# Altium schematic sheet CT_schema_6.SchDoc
size 277 x 170 mm
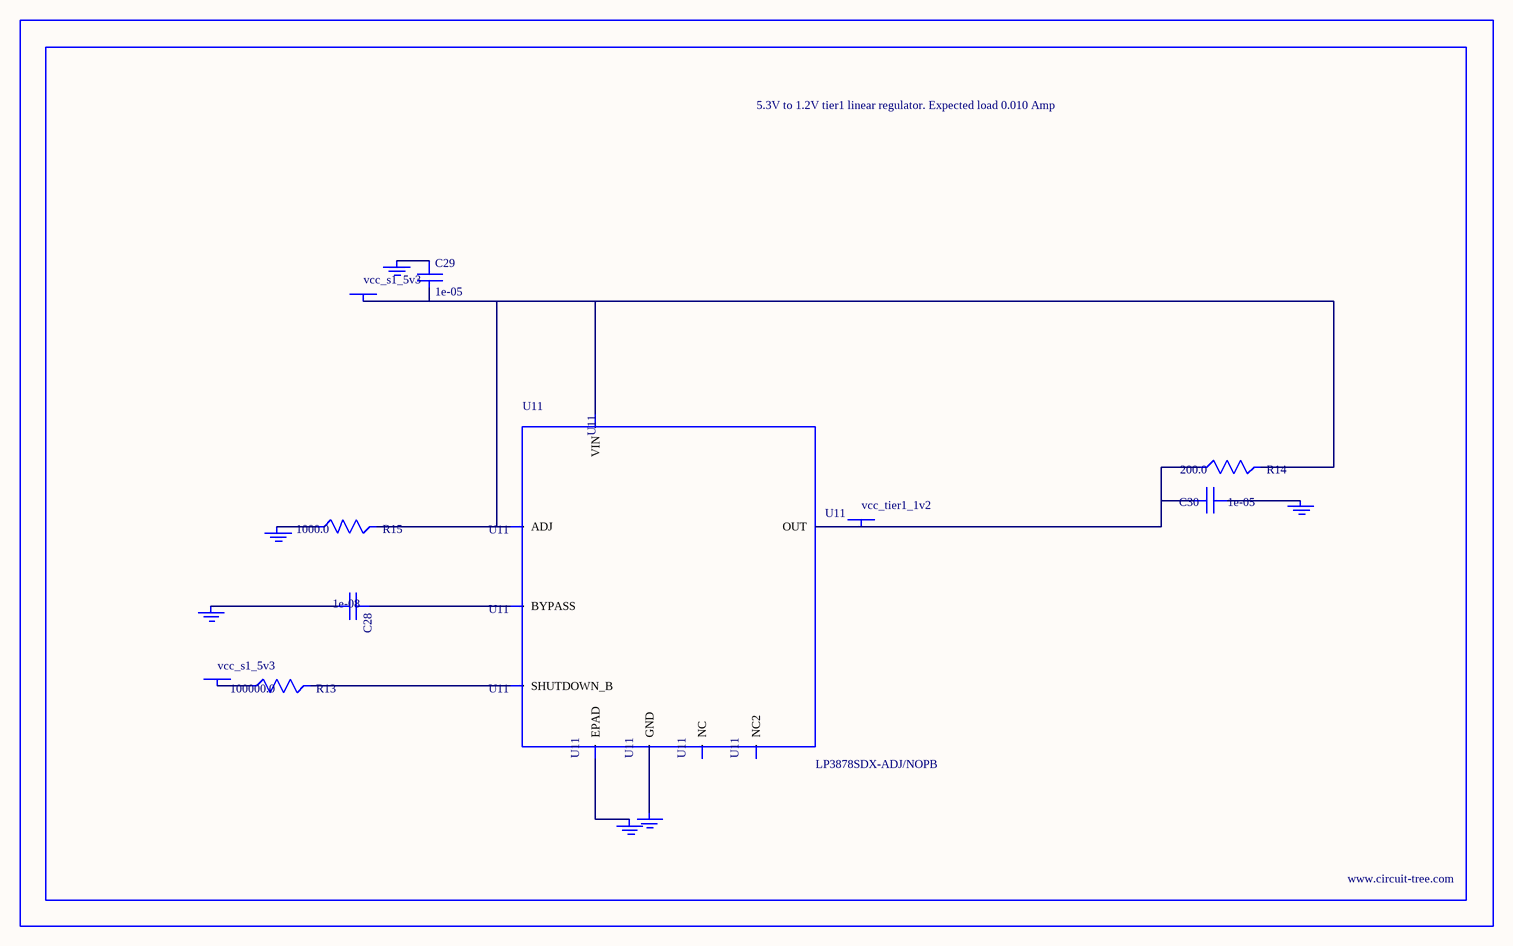
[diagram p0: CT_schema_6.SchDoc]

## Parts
BORDER5  (no value)
C28  1e-08  [C0402]
C29  1e-05  [C1206]
C30  1e-05  [C0805]
GND_INSTANCE_5_0  (no value)
GND_INSTANCE_5_1  (no value)
GND_INSTANCE_5_2  (no value)
GND_INSTANCE_5_3  (no value)
GND_INSTANCE_5_4  (no value)
GND_INSTANCE_5_5  (no value)
POWER_INSTANCE_5_0  vcc_s1_5v3
POWER_INSTANCE_5_1  vcc_s1_5v3
POWER_INSTANCE_5_2  vcc_tier1_1v2
R13  100000.0  [R0603]
R14  200.0  [R0603]
R15  1000.0  [R0603]
U11  LP3878SDX-ADJ/NOPB  [WSON-8]

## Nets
NetC28_1: C28.1 U11.1(BYPASS)
NetC28_2: C28.2 GND_INSTANCE_5_0.0(GND)
NetC29_1: C29.1 GND_INSTANCE_5_1.0(GND)
NetC29_2: C29.2 POWER_INSTANCE_5_0.0(PWR) R14.2 R15.2 U11.4(VIN) U11.6(ADJ)
NetC30_1: C30.1 GND_INSTANCE_5_2.0(GND)
NetC30_2: C30.2 POWER_INSTANCE_5_2.0(PWR) R14.1 U11.5(OUT)
NetGND_INSTANCE_5_3_0: GND_INSTANCE_5_3.0(GND) R15.1
NetGND_INSTANCE_5_4_0: GND_INSTANCE_5_4.0(GND) U11.PAD(EPAD)
NetGND_INSTANCE_5_5_0: GND_INSTANCE_5_5.0(GND) U11.3(GND)
NetPOWER_INSTANCE_5_1_0: POWER_INSTANCE_5_1.0(PWR) R13.1
NetR13_2: R13.2 U11.8(SHUTDOWN_B)

Not connected (* = marked no-connect by the designer): U11 2(NC) 7(NC2)

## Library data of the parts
BORDER5 = BORDER_PAGE5
C28 = C0402C103K3RAC
C29 = C1206C106K3RACTU
C30 = GRM219R60J106ME19D
GND_INSTANCE_5_0-GND_INSTANCE_5_5 = GND
POWER_INSTANCE_5_0-POWER_INSTANCE_5_2 = PWR
R13 = RC0603JR-07100KL
R14 = RC0603JR-07200RL
R15 = RC0603JR-071KL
